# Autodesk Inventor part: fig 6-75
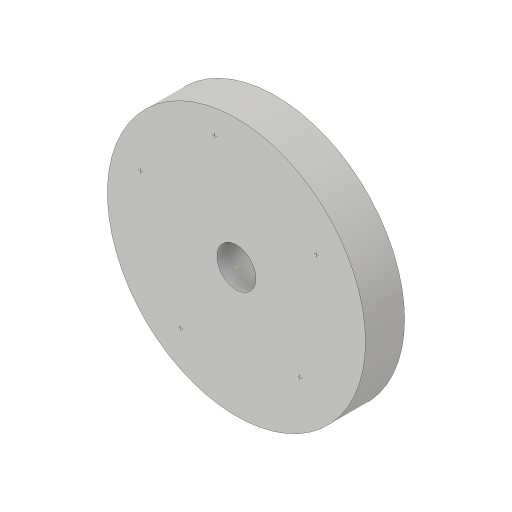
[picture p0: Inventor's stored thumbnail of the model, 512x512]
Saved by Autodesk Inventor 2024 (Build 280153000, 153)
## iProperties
Created: 2018-03
Part Number: fig 6-75
Material: Generic
Document SubType Name: Modeling
Designer: CADCIM 00
Density: 1 g/cm^3
Appearance: Default
Author: CADCIM 00
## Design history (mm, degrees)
sketch "Sketch1"
  geometry: C1 r 16.506 at (0, 0); 1 further point
  constraints: 1 centre point, 1 coincident
extrude "Extrusion1" new body sketch "Sketch1" distance "d0" = 5; taper "d1" = 0 deg
sketch "Sketch3"
  geometry: 2 further points
  constraints: 1 coincident
hole "Hole1" sketch "Sketch3" diameter "d2" = 5; stored, may be unused: countersink angle "d6" = 90 deg, drill point angle "d8" = 118 deg; dims "d3" = 6, "d4" = 4, "d5" = 2, "d7" = 8
sketch "Sketch2"
  geometry: 6 further points
body "Solid1"
